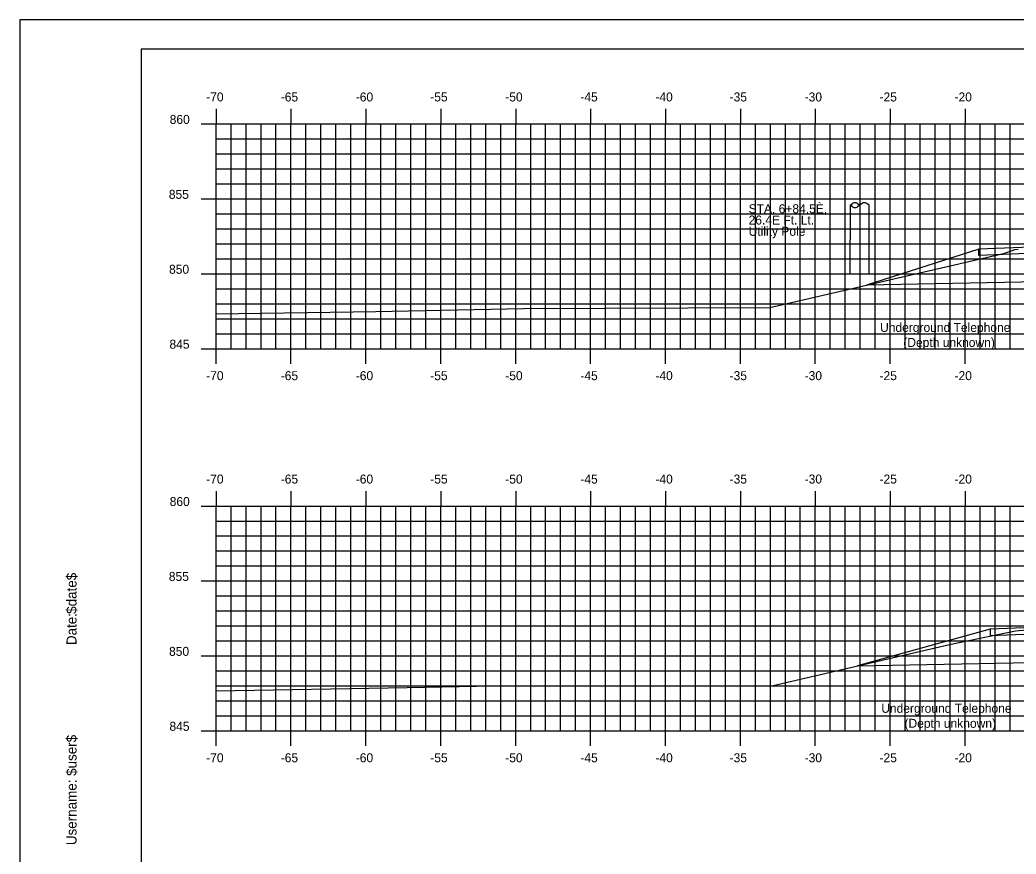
# Model space of a CAD drawing. Extents: x 2193811 to 2194294, y 863888 to 863998.
# Drawn here: x 2193950.1 to 2194016.6, y 863942.7 to 863998.4 of the extents above; entities that cross this region are included whole.
import ezdxf

# ---------------------------------------------------------------- set-up
doc = ezdxf.new("R2010")
doc.units = 0
for name, color, linetype in [('ANNOTATION', 7, 'Continuous'), ('BORDER', 7, 'Continuous'), ('D_Text_Monospaced', 7, 'Continuous'), ('H_V ANNOTATION', 7, 'Continuous'), ('MAJOR', 7, 'Continuous'), ('MINOR', 7, 'Continuous'), ('PLOT BOUNDARY', 7, 'Continuous'), ('S_Roadway_Centerline', 7, 'Continuous'), ('S_Utilities_Pole_Power', 7, 'Continuous'), ('TEMPLATE', 7, 'Continuous')]:
    doc.layers.add(name, color=color, linetype=linetype)

msp = doc.modelspace()

# ---------------------------------------------------------------- linework, layer by layer
at = {"layer": 'BORDER'}
msp.add_lwpolyline([(2193958.23, 863891.446), (2194118.23, 863891.446), (2194118.23, 863996.446), (2193958.23, 863996.446)], close=True, dxfattribs=at)
at = {"layer": 'MAJOR'}
for p, q in [((2193963.23, 863992.448), (2193963.23, 863991.446)), ((2193968.23, 863992.448), (2193968.23, 863991.446)), ((2193973.23, 863992.448), (2193973.23, 863991.446)), ((2193978.23, 863992.448), (2193978.23, 863991.446)), ((2193983.23, 863992.448), (2193983.23, 863991.446)), ((2193988.23, 863992.448), (2193988.23, 863991.446)), ((2193993.23, 863992.448), (2193993.23, 863991.446)), ((2193998.23, 863992.448), (2193998.23, 863991.446)), ((2194003.23, 863992.448), (2194003.23, 863991.446)), ((2194008.23, 863992.448), (2194008.23, 863991.446)), ((2194013.23, 863992.448), (2194013.23, 863991.446)), ((2193962.228, 863991.446), (2193963.23, 863991.446)), ((2193963.23, 863991.446), (2194103.23, 863991.446)), ((2193963.23, 863991.446), (2194103.23, 863991.446)), ((2193963.23, 863976.446), (2193963.23, 863991.446)), ((2193963.23, 863976.446), (2193963.23, 863991.446)), ((2193968.23, 863976.446), (2193968.23, 863991.446)), ((2193973.23, 863976.446), (2193973.23, 863991.446)), ((2193978.23, 863976.446), (2193978.23, 863991.446)), ((2193983.23, 863976.446), (2193983.23, 863991.446)), ((2193988.23, 863976.446), (2193988.23, 863991.446)), ((2193993.23, 863976.446), (2193993.23, 863991.446)), ((2193998.23, 863976.446), (2193998.23, 863991.446)), ((2194003.23, 863976.446), (2194003.23, 863991.446)), ((2194008.23, 863976.446), (2194008.23, 863991.446)), ((2194013.23, 863976.446), (2194013.23, 863991.446)), ((2193962.228, 863986.446), (2193963.23, 863986.446)), ((2193963.23, 863986.446), (2194103.23, 863986.446)), ((2193962.228, 863981.446), (2193963.23, 863981.446)), ((2193963.23, 863981.446), (2194103.23, 863981.446)), ((2193962.228, 863976.446), (2193963.23, 863976.446)), ((2193963.23, 863976.446), (2194103.23, 863976.446)), ((2193963.23, 863975.444), (2193963.23, 863976.446)), ((2193968.23, 863975.444), (2193968.23, 863976.446)), ((2193973.23, 863975.444), (2193973.23, 863976.446)), ((2193978.23, 863975.444), (2193978.23, 863976.446)), ((2193983.23, 863975.444), (2193983.23, 863976.446)), ((2193988.23, 863975.444), (2193988.23, 863976.446)), ((2193993.23, 863975.444), (2193993.23, 863976.446)), ((2193998.23, 863975.444), (2193998.23, 863976.446)), ((2194003.23, 863975.444), (2194003.23, 863976.446)), ((2194008.23, 863975.444), (2194008.23, 863976.446)), ((2194013.23, 863975.444), (2194013.23, 863976.446)), ((2193963.23, 863966.948), (2193963.23, 863965.946)), ((2193968.23, 863966.948), (2193968.23, 863965.946)), ((2193973.23, 863966.948), (2193973.23, 863965.946)), ((2193978.23, 863966.948), (2193978.23, 863965.946)), ((2193983.23, 863966.948), (2193983.23, 863965.946)), ((2193988.23, 863966.948), (2193988.23, 863965.946)), ((2193993.23, 863966.948), (2193993.23, 863965.946)), ((2193998.23, 863966.948), (2193998.23, 863965.946)), ((2194003.23, 863966.948), (2194003.23, 863965.946)), ((2194008.23, 863966.948), (2194008.23, 863965.946)), ((2194013.23, 863966.948), (2194013.23, 863965.946)), ((2193962.228, 863965.946), (2193963.23, 863965.946)), ((2193963.23, 863965.946), (2194103.23, 863965.946)), ((2193963.23, 863965.946), (2194103.23, 863965.946)), ((2193963.23, 863950.946), (2193963.23, 863965.946)), ((2193963.23, 863950.946), (2193963.23, 863965.946)), ((2193968.23, 863950.946), (2193968.23, 863965.946)), ((2193973.23, 863950.946), (2193973.23, 863965.946)), ((2193978.23, 863950.946), (2193978.23, 863965.946)), ((2193983.23, 863950.946), (2193983.23, 863965.946)), ((2193988.23, 863950.946), (2193988.23, 863965.946)), ((2193993.23, 863950.946), (2193993.23, 863965.946)), ((2193998.23, 863950.946), (2193998.23, 863965.946)), ((2194003.23, 863950.946), (2194003.23, 863965.946)), ((2194008.23, 863950.946), (2194008.23, 863965.946)), ((2194013.23, 863950.946), (2194013.23, 863965.946)), ((2193962.228, 863960.946), (2193963.23, 863960.946)), ((2193963.23, 863960.946), (2194103.23, 863960.946)), ((2193962.228, 863955.946), (2193963.23, 863955.946)), ((2193963.23, 863955.946), (2194103.23, 863955.946)), ((2193962.228, 863950.946), (2193963.23, 863950.946)), ((2193963.23, 863950.946), (2194103.23, 863950.946)), ((2193963.23, 863949.944), (2193963.23, 863950.946)), ((2193968.23, 863949.944), (2193968.23, 863950.946)), ((2193973.23, 863949.944), (2193973.23, 863950.946)), ((2193978.23, 863949.944), (2193978.23, 863950.946)), ((2193983.23, 863949.944), (2193983.23, 863950.946)), ((2193988.23, 863949.944), (2193988.23, 863950.946)), ((2193993.23, 863949.944), (2193993.23, 863950.946)), ((2193998.23, 863949.944), (2193998.23, 863950.946)), ((2194003.23, 863949.944), (2194003.23, 863950.946)), ((2194008.23, 863949.944), (2194008.23, 863950.946)), ((2194013.23, 863949.944), (2194013.23, 863950.946))]:
    msp.add_line(p, q, dxfattribs=at)
at = {"layer": 'MINOR'}
for p, q in [((2193964.23, 863976.446), (2193964.23, 863991.446)), ((2193965.23, 863976.446), (2193965.23, 863991.446)), ((2193966.23, 863976.446), (2193966.23, 863991.446)), ((2193967.23, 863976.446), (2193967.23, 863991.446)), ((2193969.23, 863976.446), (2193969.23, 863991.446)), ((2193970.23, 863976.446), (2193970.23, 863991.446)), ((2193971.23, 863976.446), (2193971.23, 863991.446)), ((2193972.23, 863976.446), (2193972.23, 863991.446)), ((2193974.23, 863976.446), (2193974.23, 863991.446)), ((2193975.23, 863976.446), (2193975.23, 863991.446)), ((2193976.23, 863976.446), (2193976.23, 863991.446)), ((2193977.23, 863976.446), (2193977.23, 863991.446)), ((2193979.23, 863976.446), (2193979.23, 863991.446)), ((2193980.23, 863976.446), (2193980.23, 863991.446)), ((2193981.23, 863976.446), (2193981.23, 863991.446)), ((2193982.23, 863976.446), (2193982.23, 863991.446)), ((2193984.23, 863976.446), (2193984.23, 863991.446)), ((2193985.23, 863976.446), (2193985.23, 863991.446)), ((2193986.23, 863976.446), (2193986.23, 863991.446)), ((2193987.23, 863976.446), (2193987.23, 863991.446)), ((2193989.23, 863976.446), (2193989.23, 863991.446)), ((2193990.23, 863976.446), (2193990.23, 863991.446)), ((2193991.23, 863976.446), (2193991.23, 863991.446)), ((2193992.23, 863976.446), (2193992.23, 863991.446)), ((2193994.23, 863976.446), (2193994.23, 863991.446)), ((2193995.23, 863976.446), (2193995.23, 863991.446)), ((2193996.23, 863976.446), (2193996.23, 863991.446)), ((2193997.23, 863976.446), (2193997.23, 863991.446)), ((2193999.23, 863976.446), (2193999.23, 863991.446)), ((2194000.23, 863976.446), (2194000.23, 863991.446)), ((2194001.23, 863976.446), (2194001.23, 863991.446)), ((2194002.23, 863976.446), (2194002.23, 863991.446)), ((2194004.23, 863976.446), (2194004.23, 863991.446)), ((2194005.23, 863976.446), (2194005.23, 863991.446)), ((2194006.23, 863976.446), (2194006.23, 863991.446)), ((2194007.23, 863976.446), (2194007.23, 863991.446)), ((2194009.23, 863976.446), (2194009.23, 863991.446)), ((2194010.23, 863976.446), (2194010.23, 863991.446)), ((2194011.23, 863976.446), (2194011.23, 863991.446)), ((2194012.23, 863976.446), (2194012.23, 863991.446)), ((2194014.23, 863976.446), (2194014.23, 863991.446)), ((2194015.23, 863976.446), (2194015.23, 863991.446)), ((2194016.23, 863976.446), (2194016.23, 863991.446)), ((2193963.23, 863990.446), (2194103.23, 863990.446)), ((2193963.23, 863990.446), (2193964.232, 863990.446)), ((2193963.23, 863989.446), (2194103.23, 863989.446)), ((2193963.23, 863989.446), (2193964.232, 863989.446)), ((2193963.23, 863988.446), (2194103.23, 863988.446)), ((2193963.23, 863988.446), (2193964.232, 863988.446)), ((2193963.23, 863987.446), (2194103.23, 863987.446)), ((2193963.23, 863987.446), (2193964.232, 863987.446)), ((2193963.23, 863985.446), (2194103.23, 863985.446)), ((2193963.23, 863985.446), (2193964.232, 863985.446)), ((2193963.23, 863984.446), (2194103.23, 863984.446)), ((2193963.23, 863984.446), (2193964.232, 863984.446)), ((2193963.23, 863983.446), (2194103.23, 863983.446)), ((2193963.23, 863983.446), (2193964.232, 863983.446)), ((2193963.23, 863982.446), (2194103.23, 863982.446)), ((2193963.23, 863982.446), (2193964.232, 863982.446)), ((2193963.23, 863980.446), (2194103.23, 863980.446)), ((2193963.23, 863980.446), (2193964.232, 863980.446)), ((2193963.23, 863979.446), (2194103.23, 863979.446)), ((2193963.23, 863979.446), (2193964.232, 863979.446)), ((2193963.23, 863978.446), (2194103.23, 863978.446)), ((2193963.23, 863978.446), (2193964.232, 863978.446)), ((2193963.23, 863977.446), (2194103.23, 863977.446)), ((2193963.23, 863977.446), (2193964.232, 863977.446)), ((2193964.23, 863950.946), (2193964.23, 863965.946)), ((2193965.23, 863950.946), (2193965.23, 863965.946)), ((2193966.23, 863950.946), (2193966.23, 863965.946)), ((2193967.23, 863950.946), (2193967.23, 863965.946)), ((2193969.23, 863950.946), (2193969.23, 863965.946)), ((2193970.23, 863950.946), (2193970.23, 863965.946)), ((2193971.23, 863950.946), (2193971.23, 863965.946)), ((2193972.23, 863950.946), (2193972.23, 863965.946)), ((2193974.23, 863950.946), (2193974.23, 863965.946)), ((2193975.23, 863950.946), (2193975.23, 863965.946)), ((2193976.23, 863950.946), (2193976.23, 863965.946)), ((2193977.23, 863950.946), (2193977.23, 863965.946)), ((2193979.23, 863950.946), (2193979.23, 863965.946)), ((2193980.23, 863950.946), (2193980.23, 863965.946)), ((2193981.23, 863950.946), (2193981.23, 863965.946)), ((2193982.23, 863950.946), (2193982.23, 863965.946)), ((2193984.23, 863950.946), (2193984.23, 863965.946)), ((2193985.23, 863950.946), (2193985.23, 863965.946)), ((2193986.23, 863950.946), (2193986.23, 863965.946)), ((2193987.23, 863950.946), (2193987.23, 863965.946)), ((2193989.23, 863950.946), (2193989.23, 863965.946)), ((2193990.23, 863950.946), (2193990.23, 863965.946)), ((2193991.23, 863950.946), (2193991.23, 863965.946)), ((2193992.23, 863950.946), (2193992.23, 863965.946)), ((2193994.23, 863950.946), (2193994.23, 863965.946)), ((2193995.23, 863950.946), (2193995.23, 863965.946)), ((2193996.23, 863950.946), (2193996.23, 863965.946)), ((2193997.23, 863950.946), (2193997.23, 863965.946)), ((2193999.23, 863950.946), (2193999.23, 863965.946)), ((2194000.23, 863950.946), (2194000.23, 863965.946)), ((2194001.23, 863950.946), (2194001.23, 863965.946)), ((2194002.23, 863950.946), (2194002.23, 863965.946)), ((2194004.23, 863950.946), (2194004.23, 863965.946)), ((2194005.23, 863950.946), (2194005.23, 863965.946)), ((2194006.23, 863950.946), (2194006.23, 863965.946)), ((2194007.23, 863950.946), (2194007.23, 863965.946)), ((2194009.23, 863950.946), (2194009.23, 863965.946)), ((2194010.23, 863950.946), (2194010.23, 863965.946)), ((2194011.23, 863950.946), (2194011.23, 863965.946)), ((2194012.23, 863950.946), (2194012.23, 863965.946)), ((2194014.23, 863950.946), (2194014.23, 863965.946)), ((2194015.23, 863950.946), (2194015.23, 863965.946)), ((2194016.23, 863950.946), (2194016.23, 863965.946)), ((2193963.23, 863964.946), (2194103.23, 863964.946)), ((2193963.23, 863964.946), (2193964.232, 863964.946)), ((2193963.23, 863963.946), (2194103.23, 863963.946)), ((2193963.23, 863963.946), (2193964.232, 863963.946)), ((2193963.23, 863962.946), (2194103.23, 863962.946)), ((2193963.23, 863962.946), (2193964.232, 863962.946)), ((2193963.23, 863961.946), (2194103.23, 863961.946)), ((2193963.23, 863961.946), (2193964.232, 863961.946)), ((2193963.23, 863959.946), (2194103.23, 863959.946)), ((2193963.23, 863959.946), (2193964.232, 863959.946)), ((2193963.23, 863958.946), (2194103.23, 863958.946)), ((2193963.23, 863958.946), (2193964.232, 863958.946)), ((2193963.23, 863957.946), (2194103.23, 863957.946)), ((2193963.23, 863957.946), (2193964.232, 863957.946)), ((2193963.23, 863956.946), (2194103.23, 863956.946)), ((2193963.23, 863956.946), (2193964.232, 863956.946)), ((2193963.23, 863954.946), (2194103.23, 863954.946)), ((2193963.23, 863954.946), (2193964.232, 863954.946)), ((2193963.23, 863953.946), (2194103.23, 863953.946)), ((2193963.23, 863953.946), (2193964.232, 863953.946)), ((2193963.23, 863952.946), (2194103.23, 863952.946)), ((2193963.23, 863952.946), (2193964.232, 863952.946)), ((2193963.23, 863951.946), (2194103.23, 863951.946)), ((2193963.23, 863951.946), (2193964.232, 863951.946))]:
    msp.add_line(p, q, dxfattribs=at)
at = {"layer": 'PLOT BOUNDARY'}
msp.add_lwpolyline([(2193950.137, 863888.387), (2194120.137, 863888.387), (2194120.137, 863998.387), (2193950.137, 863998.387)], close=True, dxfattribs=at)
at = {"layer": 'S_Roadway_Centerline'}
for points in [[(2193963.23, 863978.769), (2193973.888, 863978.938), (2193983.752, 863979.138), (2194000.197, 863979.187), (2194015.508, 863982.725), (2194015.888, 863982.827), (2194016.557, 863983.055), (2194016.765, 863983.092)], [(2193963.23, 863953.622), (2193975.976, 863953.825), (2193980.625, 863953.919), (2194000.427, 863953.978), (2194012.195, 863956.697), (2194016.591, 863957.61), (2194017.347, 863957.685)]]:
    msp.add_lwpolyline(points, dxfattribs=at)
at = {"layer": 'S_Utilities_Pole_Power'}
for p, q in [((2194005.567, 863986.025), (2194005.724, 863986.136)), ((2194005.567, 863981.406), (2194005.571, 863986.025)), ((2194005.724, 863985.914), (2194005.567, 863986.025)), ((2194006.036, 863986.136), (2194006.193, 863986.025)), ((2194006.193, 863986.025), (2194006.036, 863985.914)), ((2194006.349, 863986.136), (2194006.193, 863986.025)), ((2194006.817, 863986.025), (2194006.661, 863986.136)), ((2194006.817, 863981.406), (2194006.821, 863986.025))]:
    msp.add_line(p, q, dxfattribs=at)
for centre, start, end in [((2194005.88, 863985.915), 90, 125.26439), ((2194005.88, 863986.136), 234.73561, 270), ((2194005.88, 863985.915), 54.73561, 90), ((2194005.88, 863986.136), 270, 305.26439), ((2194006.505, 863985.915), 90, 125.26439), ((2194006.505, 863985.915), 54.73561, 90)]:
    msp.add_arc(centre, 0.271, start, end, dxfattribs=at)
at = {"layer": 'TEMPLATE'}
for p, q in [((2194022.23, 863983.406), (2194014.139, 863983.082)), ((2194016.23, 863983.166), (2194016.23, 863983.166)), ((2194014.139, 863983.082), (2194006.648, 863980.677)), ((2194033.23, 863981.209), (2194006.648, 863980.677)), ((2194014.902, 863957.723), (2194006.042, 863955.275))]:
    msp.add_line(p, q, dxfattribs=at)
for points in [[(2194022.23, 863982.989), (2194014.139, 863982.665), (2194014.139, 863983.082)], [(2194050.895, 863957.749), (2194044.23, 863958.016), (2194033.23, 863958.236), (2194022.23, 863958.016), (2194014.902, 863957.723)], [(2194014.902, 863957.723), (2194014.902, 863957.306), (2194022.23, 863957.599)], [(2194006.042, 863955.275), (2194022.23, 863955.599), (2194033.23, 863955.819), (2194044.23, 863955.599), (2194063.388, 863955.216)]]:
    msp.add_lwpolyline(points, dxfattribs=at)

# ---------------------------------------------------------------- texts
at = {"layer": 'ANNOTATION'}
for s, p in [('Underground Telephone', (2194007.555, 863977.565)), ('(Depth unknown)', (2194009.105, 863976.563)), ('Underground Telephone', (2194007.632, 863952.147)), ('(Depth unknown)', (2194009.182, 863951.145))]:
    msp.add_text(s, height=0.6, dxfattribs=at).set_placement(p)
at = {"layer": 'BORDER'}
for s, p in [('$date$', (2193953.915, 863958.751)), ('Date:', (2193953.915, 863956.663)), ('$user$', (2193953.915, 863947.937)), ('Username:', (2193953.915, 863943.314))]:
    msp.add_text(s, height=0.6696, rotation=90, dxfattribs=at).set_placement(p)
at = {"layer": 'D_Text_Monospaced'}
for s, p in [('STA. 6+84.5È,', (2193998.779, 863985.485)), ('26.4È Ft. Lt.', (2193998.779, 863984.733)), ('Utility Pole', (2193998.779, 863983.982))]:
    msp.add_text(s, height=0.59998, dxfattribs=at).set_placement(p)
at = {"layer": 'H_V ANNOTATION'}
for s, p in [('-70', (2193962.571, 863992.946)), ('-65', (2193967.547, 863992.946)), ('-60', (2193972.555, 863992.946)), ('-55', (2193977.526, 863992.946)), ('-50', (2193982.534, 863992.946)), ('-45', (2193987.547, 863992.946)), ('-40', (2193992.555, 863992.946)), ('-35', (2193997.51, 863992.946)), ('-30', (2194002.518, 863992.946)), ('-25', (2194007.515, 863992.946)), ('-20', (2194012.523, 863992.946)), ('860', (2193960.135, 863991.446)), ('855', (2193960.076, 863986.446)), ('850', (2193960.092, 863981.446)), ('845', (2193960.119, 863976.446)), ('-70', (2193962.571, 863974.346)), ('-65', (2193967.547, 863974.346)), ('-60', (2193972.555, 863974.346)), ('-55', (2193977.526, 863974.346)), ('-50', (2193982.534, 863974.346)), ('-45', (2193987.547, 863974.346)), ('-40', (2193992.555, 863974.346)), ('-35', (2193997.51, 863974.346)), ('-30', (2194002.518, 863974.346)), ('-25', (2194007.515, 863974.346)), ('-20', (2194012.523, 863974.346)), ('-70', (2193962.571, 863967.446)), ('-65', (2193967.547, 863967.446)), ('-60', (2193972.555, 863967.446)), ('-55', (2193977.526, 863967.446)), ('-50', (2193982.534, 863967.446)), ('-45', (2193987.547, 863967.446)), ('-40', (2193992.555, 863967.446)), ('-35', (2193997.51, 863967.446)), ('-30', (2194002.518, 863967.446)), ('-25', (2194007.515, 863967.446)), ('-20', (2194012.523, 863967.446)), ('860', (2193960.135, 863965.946)), ('855', (2193960.076, 863960.946)), ('850', (2193960.092, 863955.946)), ('845', (2193960.119, 863950.946)), ('-70', (2193962.571, 863948.846)), ('-65', (2193967.547, 863948.846)), ('-60', (2193972.555, 863948.846)), ('-55', (2193977.526, 863948.846)), ('-50', (2193982.534, 863948.846)), ('-45', (2193987.547, 863948.846)), ('-40', (2193992.555, 863948.846)), ('-35', (2193997.51, 863948.846)), ('-30', (2194002.518, 863948.846)), ('-25', (2194007.515, 863948.846)), ('-20', (2194012.523, 863948.846))]:
    msp.add_text(s, height=0.6, dxfattribs=at).set_placement(p)

doc.saveas('drawing.dxf')
